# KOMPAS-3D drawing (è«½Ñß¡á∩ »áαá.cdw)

Referenced files in C:\Documents and Settings\rwlib\Мои документы\Контент для сайта pomogala\Дипломные работы\Тема № 4 Колесная пара электровоза\: Колесная пара электровоза.tif
Referenced files in C:\Documents and Settings\Чертёжник\Мои документы\Мои работы для шараги\Работы и заготовки для них\Ремонт колесных пар\: Колесная пара.cdw
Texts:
  Вставь свой шифр
  Колесная пара
  Александр Иванович
  Домашний компьютер
  Текст на чертеже
  Размерные надписи
  Шероховатость
  Линия-выноска #1
  Линия-выноска #2
  Линия-выноска #3
  Отклонения формы и база
  Заголовок таблицы
  Ячейка таблицы
  Стрелка вида
  Обозначение изменения
  Фигурная скобка
  Номер узла
  Марка координационной оси
  VRCB
  Выносная надпись
  Обозначение узла
  Марка/позиционное обозначение с линией-выноской
  Марка/позиционное обозначение на линии
  Марка/позиционное обозначение без линии-выноски
  Слой 1
  Колесная пара электровоза.tif
  Иванов
  ПЭР.30.04.00.00.09.СБ-
Dimensions and other numbers on the sheet: 7; 1098; 1440; 140; 1250; 1; 2; 3; 4; 5; 0; 6; 8; 9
